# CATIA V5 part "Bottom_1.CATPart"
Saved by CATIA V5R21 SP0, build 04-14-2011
Part number: Part1.3
Material "DS Light Blue": density 7860 kg/m3, Young's modulus 2e+11 Pa, Poisson ratio 0.266
Bounding box of the stored display mesh (mm): x 0 to 30, y -32 to 32, z -31.99 to 31.99
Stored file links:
  C:\Users\RIAD MAHAMUD PIASH\Desktop\Project\Bottom_1.CATPart
  C:\Program Files (x86)\Dassault Systemes\B21\intel_a\startup\materials\blue_env_512x512.jpg
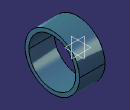
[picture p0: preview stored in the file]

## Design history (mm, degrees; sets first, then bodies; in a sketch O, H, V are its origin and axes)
Body1 (main body), material "DS Light Blue"
  Sketch1 on yz-plane, origin (0, 0, 0), H (0, 1, 0), V (0, 0, 1)
    circle A1 centre (0, 0) radius 27.5
    circle A2 centre (0, 0) radius 32
    radius A1 = 27.5
    radius A2 = 32
  Pad1: profile Sketch1, direction (1, 0, 0), length 30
